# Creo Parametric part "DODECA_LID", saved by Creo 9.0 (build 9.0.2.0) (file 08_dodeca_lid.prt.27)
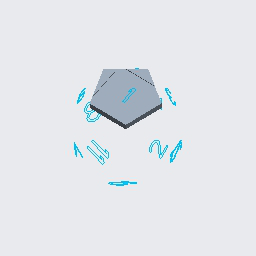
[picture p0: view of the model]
Units: millimeter Kilogram Sec (mmKs); MM, KILOGRAM, SECS

Created from: DODECA_STYLUS_HALF.PRT

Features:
  1. coordinate system
  2. datum plane "RIGHT"
  3. datum plane "TOP"
  4. datum plane "FRONT"
  5. protrusion
  6. cut
  7. cut
  8. curve
  9. cut
  10. datum axis
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
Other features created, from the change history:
  chamfer "Chamfer 1"
  round "Round 1"
  round "Round 2"
  round "Round 3"
  round "Round 4"
  round "Round 5"
  extrusion "Extrude 18"
  extrusion "Extrude 19"
  extruded cut "Extrude 20"
  extruded cut "Extrude 21"
  extruded cut "Extrude 22"
  extruded cut "Extrude 23"
  extrusion "Extrude 24"
  extrusion "Extrude 25" (2 times)
  extruded cut "Extrude 26"
  extruded cut "Extrude 27"
  extruded cut "Extrude 28"
  extrusion "Extrude 29"
  extruded cut "Extrude 30"
  extruded cut "Extrude 31"

Other named items: DEFAULT_1, DEFAULT_2, DEFAULT_3, DEFAULT_4, DEFAULT_5, DEFAULT_6, DEFAULT_7, DEFAULT_8, DEFAULT_9, DEFAULT_10, DEFAULT_11, DEFAULT_12, DEFAULT_13, DEFAULT_14, DEFAULT_15, DEFAULT_16, DEFAULT_17, DEFAULT_18, DEFAULT_19, DEFAULT_20, DEFAULT_21, DEFAULT_22, DEFAULT_23, DEFAULT_24

Surfaces: 13 plane, 2 cylinder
